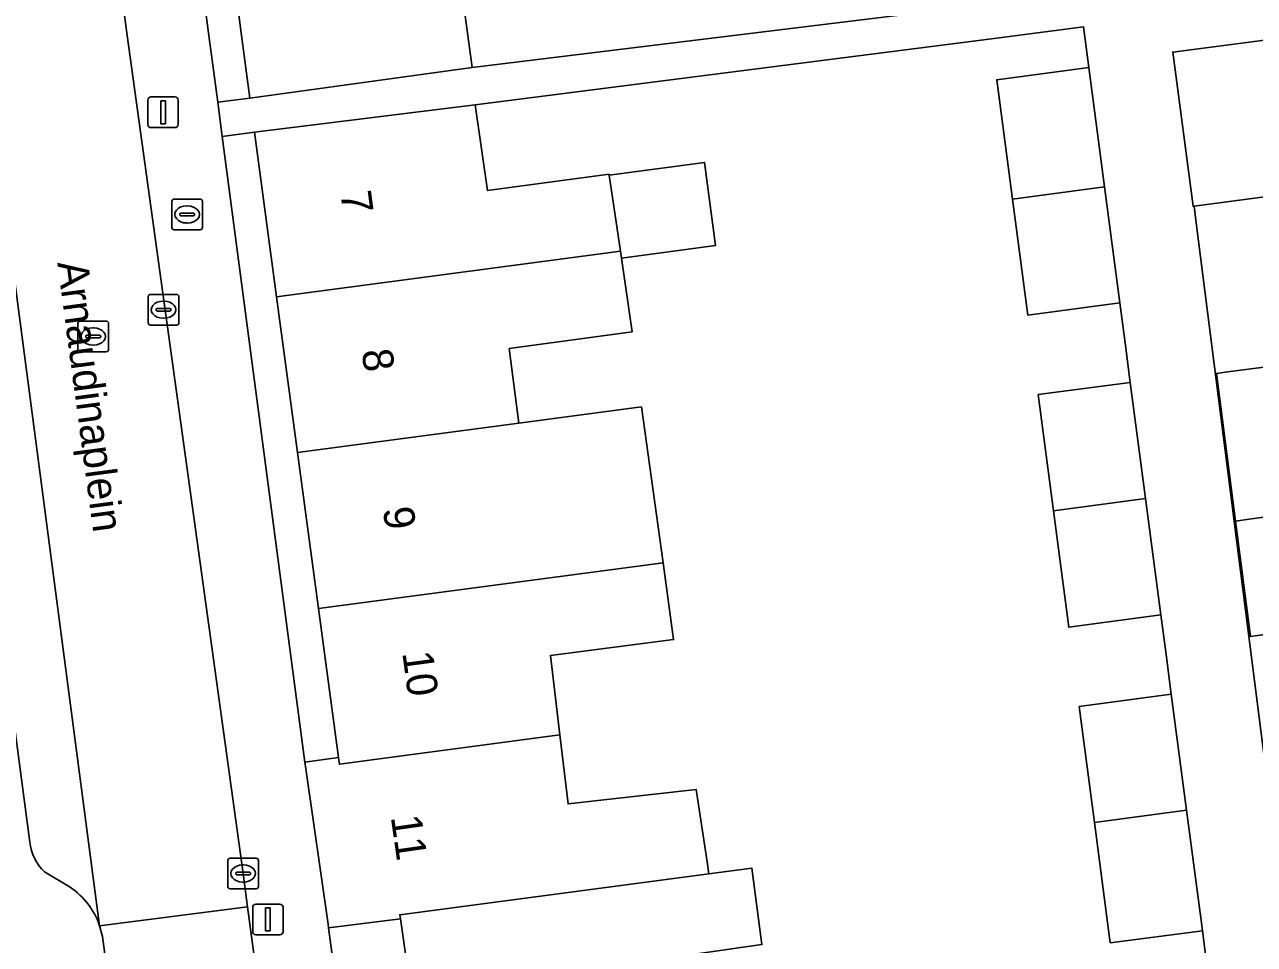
# Model space of a CAD drawing. Extents: x 163147 to 163550, y 380933 to 381639.
# Drawn here: x 163423.12 to 163463.29, y 381220.32 to 381250.36 of the extents above; entities that cross this region are included whole.
import ezdxf

# ---------------------------------------------------------------- set-up
doc = ezdxf.new("R2010")
doc.units = 0
for name, color, linetype in [('IMGEO_Brandkraan', 7, 'Continuous'), ('IMGEO_Erf', 7, 'Continuous'), ('IMGEO_Kolk', 7, 'Continuous'), ('IMGEO_Lichtmast', 7, 'Continuous'), ('IMGEO_Openbare_ruimte_label', 7, 'Continuous'), ('IMGEO_Pand', 7, 'Continuous'), ('IMGEO_Pand_nummerreeks', 7, 'Continuous'), ('IMGEO_Parkeervlak_open', 7, 'Continuous'), ('IMGEO_Rijbaan_lokaal_open', 7, 'Continuous'), ('IMGEO_Rioolput', 7, 'Continuous'), ('IMGEO_Voetpad_open', 7, 'Continuous')]:
    doc.layers.add(name, color=color, linetype=linetype)

msp = doc.modelspace()

# ---------------------------------------------------------------- linework, layer by layer
at = {"layer": 'IMGEO_Brandkraan'}
for p, q in [((163427.933, 381243.732), (163427.933, 381244.584)), ((163428.008, 381244.658), (163428.86, 381244.658)), ((163428.421, 381244.438), (163428.446, 381244.438)), ((163428.934, 381244.584), (163428.934, 381243.732)), ((163428.192, 381244.152), (163428.192, 381244.164)), ((163428.63, 381244.115), (163428.232, 381244.115)), ((163428.235, 381244.201), (163428.633, 381244.201)), ((163428.676, 381244.164), (163428.676, 381244.152)), ((163428.86, 381243.658), (163428.008, 381243.658)), ((163428.444, 381243.878), (163428.419, 381243.878))]:
    msp.add_line(p, q, dxfattribs=at)
for points in [[(163427.933, 381243.732), (163427.933, 381244.584)], [(163428.008, 381244.658), (163428.86, 381244.658)], [(163428.934, 381244.584), (163428.934, 381243.732)], [(163428.86, 381243.658), (163428.008, 381243.658)]]:
    msp.add_lwpolyline(points, dxfattribs=at)
for centre, radius, start, end in [((163428.01, 381244.582), 0.0765, 91.552, 178.448), ((163428.01, 381244.582), 0.0765, 91.552, 178.448), ((163428.858, 381244.582), 0.0765, 1.552, 88.448), ((163428.858, 381244.582), 0.0765, 1.552, 88.448), ((163428.232, 381244.161), 0.0403, 85.8775, 175.7526), ((163428.229, 381244.151), 0.0366, 178.938, 274.7102), ((163428.633, 381244.158), 0.043, 264.8664, 352.4533), ((163428.637, 381244.163), 0.0386, 1.7309, 96.639), ((163428.01, 381243.734), 0.0765, 181.552, 268.448), ((163428.01, 381243.734), 0.0765, 181.552, 268.448), ((163428.858, 381243.734), 0.0765, 271.552, 358.448), ((163428.858, 381243.734), 0.0765, 271.552, 358.448)]:
    msp.add_arc(centre, radius, start, end, dxfattribs=at)
for centre, major_axis, ratio, start_param, end_param in [((163428.42, 381244.158), (-0.387, 0.002), 0.722429, 4.712389, 7.853982), ((163428.445, 381244.158), (-0.39, 0.002), 0.717154, 1.570796, 4.712389)]:
    msp.add_ellipse(centre, major_axis=major_axis, ratio=ratio, start_param=start_param, end_param=end_param, dxfattribs=at)
at = {"layer": 'IMGEO_Erf'}
for points in [[(163428.498, 381263.148), (163427.838, 381268.207), (163426.754, 381268.057), (163429.143, 381250), (163429.432, 381247.82), (163430.478, 381247.959), (163430.212, 381250), (163429.825, 381252.969), (163429.161, 381258.058)], [(163431.352, 381241.467), (163430.629, 381246.841), (163429.579, 381246.702), (163432.283, 381226.275), (163433.376, 381226.422), (163432.721, 381231.291), (163432.037, 381236.379)], [(163465.674, 381234.559), (163466.161, 381230.788), (163463.165, 381230.376), (163462.678, 381234.147), (163462.055, 381238.969), (163462.505, 381239.027), (163465.054, 381239.356)], [(163435.398, 381221.16), (163433.055, 381220.865), (163433.713, 381215.942), (163436.097, 381216.261)]]:
    msp.add_lwpolyline(points, close=True, dxfattribs=at)
for points in [[(163437.371, 381251.695), (163437.604, 381250), (163437.747, 381248.957), (163457.58, 381251.397)], [(163461.71, 381219.908), (163461.597, 381220.769), (163458.588, 381220.373), (163458.532, 381220.791), (163458.07, 381224.302), (163457.572, 381228.088), (163460.58, 381228.488), (163460.409, 381229.79), (163460.239, 381231.079), (163457.231, 381230.679), (163456.731, 381234.48), (163456.231, 381238.275), (163459.24, 381238.674), (163459.07, 381239.968), (163458.899, 381241.268), (163455.89, 381240.869), (163455.392, 381244.658), (163454.879, 381248.558), (163457.887, 381248.955), (163457.712, 381250.283), (163454.704, 381249.887), (163437.843, 381247.74), (163438.242, 381244.937), (163442.214, 381245.472), (163442.219, 381245.44), (163445.335, 381245.854), (163445.695, 381243.147), (163442.618, 381242.733), (163442.972, 381240.326), (163438.955, 381239.775), (163439.267, 381237.339), (163443.273, 381237.871), (163443.977, 381232.786), (163444.325, 381230.277), (163440.299, 381229.756), (163440.61, 381227.16), (163440.879, 381224.909), (163445.064, 381225.378), (163445.419, 381223.013), (163445.477, 381222.629), (163446.874, 381222.815), (163447.21, 381220.316)], [(163464.284, 381244.821), (163461.325, 381244.431), (163461.395, 381243.883), (163465.785, 381209.444)]]:
    msp.add_lwpolyline(points, dxfattribs=at)
at = {"layer": 'IMGEO_Kolk'}
for p, q in [((163427.162, 381240.621), (163427.162, 381241.473)), ((163427.237, 381241.547), (163428.089, 381241.547)), ((163427.65, 381241.327), (163427.675, 381241.327)), ((163428.163, 381241.473), (163428.163, 381240.621)), ((163427.421, 381241.041), (163427.421, 381241.053)), ((163427.859, 381241.004), (163427.461, 381241.004)), ((163427.464, 381241.09), (163427.862, 381241.09)), ((163427.905, 381241.053), (163427.905, 381241.041)), ((163428.089, 381240.547), (163427.237, 381240.547)), ((163427.673, 381240.767), (163427.648, 381240.767)), ((163429.761, 381222.21), (163429.761, 381223.062)), ((163429.836, 381223.136), (163430.688, 381223.136)), ((163430.249, 381222.916), (163430.274, 381222.916)), ((163430.762, 381223.062), (163430.762, 381222.21)), ((163430.02, 381222.63), (163430.02, 381222.642)), ((163430.458, 381222.593), (163430.06, 381222.593)), ((163430.063, 381222.679), (163430.461, 381222.679)), ((163430.272, 381222.356), (163430.247, 381222.356)), ((163430.504, 381222.642), (163430.504, 381222.63)), ((163430.688, 381222.136), (163429.836, 381222.136))]:
    msp.add_line(p, q, dxfattribs=at)
for points in [[(163427.162, 381240.621), (163427.162, 381241.473)], [(163427.237, 381241.547), (163428.089, 381241.547)], [(163428.163, 381241.473), (163428.163, 381240.621)], [(163428.089, 381240.547), (163427.237, 381240.547)], [(163429.761, 381222.21), (163429.761, 381223.062)], [(163429.836, 381223.136), (163430.688, 381223.136)], [(163430.762, 381223.062), (163430.762, 381222.21)], [(163430.688, 381222.136), (163429.836, 381222.136)]]:
    msp.add_lwpolyline(points, dxfattribs=at)
for centre, radius, start, end in [((163427.239, 381241.471), 0.0765, 91.552, 178.448), ((163427.239, 381241.471), 0.0765, 91.552, 178.448), ((163428.087, 381241.471), 0.0765, 1.552, 88.448), ((163428.087, 381241.471), 0.0765, 1.552, 88.448), ((163427.461, 381241.05), 0.0403, 85.8775, 175.7526), ((163427.458, 381241.04), 0.0366, 178.938, 274.7102), ((163427.862, 381241.047), 0.043, 264.8664, 352.4533), ((163427.866, 381241.052), 0.0386, 1.7309, 96.639), ((163427.239, 381240.623), 0.0765, 181.552, 268.448), ((163427.239, 381240.623), 0.0765, 181.552, 268.448), ((163428.087, 381240.623), 0.0765, 271.552, 358.448), ((163428.087, 381240.623), 0.0765, 271.552, 358.448), ((163429.838, 381223.06), 0.0765, 91.552, 178.448), ((163429.838, 381223.06), 0.0765, 91.552, 178.448), ((163430.686, 381223.06), 0.0765, 1.552, 88.448), ((163430.686, 381223.06), 0.0765, 1.552, 88.448), ((163430.06, 381222.639), 0.0403, 85.8775, 175.7526), ((163430.057, 381222.629), 0.0366, 178.938, 274.7102), ((163430.461, 381222.636), 0.043, 264.8664, 352.4533), ((163430.465, 381222.641), 0.0386, 1.7309, 96.639), ((163429.838, 381222.212), 0.0765, 181.552, 268.448), ((163429.838, 381222.212), 0.0765, 181.552, 268.448), ((163430.686, 381222.212), 0.0765, 271.552, 358.448), ((163430.686, 381222.212), 0.0765, 271.552, 358.448)]:
    msp.add_arc(centre, radius, start, end, dxfattribs=at)
for centre, major_axis, ratio, start_param, end_param in [((163427.649, 381241.047), (-0.387, 0.002), 0.722429, 4.712389, 7.853982), ((163427.674, 381241.047), (-0.39, 0.002), 0.717154, 1.570796, 4.712389), ((163430.248, 381222.636), (-0.387, 0.002), 0.722429, 4.712389, 7.853982), ((163430.273, 381222.636), (-0.39, 0.002), 0.717154, 1.570796, 4.712389)]:
    msp.add_ellipse(centre, major_axis=major_axis, ratio=ratio, start_param=start_param, end_param=end_param, dxfattribs=at)
at = {"layer": 'IMGEO_Lichtmast'}
for p, q in [((163427.152, 381247.093), (163427.152, 381247.893)), ((163427.152, 381247.893), (163427.152, 381247.093)), ((163427.252, 381247.993), (163428.042, 381247.993)), ((163428.042, 381247.993), (163427.252, 381247.993)), ((163428.142, 381247.893), (163428.142, 381247.093)), ((163428.142, 381247.093), (163428.142, 381247.893)), ((163428.042, 381246.993), (163427.252, 381246.993)), ((163427.252, 381246.993), (163428.042, 381246.993)), ((163430.575, 381220.736), (163430.575, 381221.536)), ((163430.575, 381221.536), (163430.575, 381220.736)), ((163430.675, 381221.636), (163431.465, 381221.636)), ((163431.465, 381221.636), (163430.675, 381221.636)), ((163431.565, 381221.536), (163431.565, 381220.736)), ((163431.565, 381220.736), (163431.565, 381221.536)), ((163431.465, 381220.636), (163430.675, 381220.636)), ((163430.675, 381220.636), (163431.465, 381220.636))]:
    msp.add_line(p, q, dxfattribs=at)
for points in [[(163427.572, 381247.868), (163427.722, 381247.868), (163427.722, 381247.118), (163427.572, 381247.118), (163427.572, 381247.868)], [(163430.995, 381221.511), (163431.145, 381221.511), (163431.145, 381220.761), (163430.995, 381220.761), (163430.995, 381221.511)]]:
    msp.add_lwpolyline(points, dxfattribs=at)
for centre, start, end in [((163427.252, 381247.893), 90, 180), ((163427.252, 381247.893), 90, 180), ((163428.042, 381247.893), 0, 90), ((163428.042, 381247.893), 360, 90), ((163427.252, 381247.093), 180, 270), ((163427.252, 381247.093), 180, 270), ((163428.042, 381247.093), 270, 0), ((163428.042, 381247.093), 270, 0), ((163430.675, 381221.536), 90, 180), ((163430.675, 381221.536), 90, 180), ((163431.465, 381221.536), 0, 90), ((163431.465, 381221.536), 360, 90), ((163430.675, 381220.736), 180, 270), ((163430.675, 381220.736), 180, 270), ((163431.465, 381220.736), 270, 0), ((163431.465, 381220.736), 270, 0)]:
    msp.add_arc(centre, 0.1, start, end, dxfattribs=at)
at = {"layer": 'IMGEO_Pand'}
for points in [[(163441.11, 381254.487), (163429.825, 381252.969), (163430.212, 381250), (163430.478, 381247.959), (163437.747, 381248.957), (163437.604, 381250), (163437.371, 381251.695), (163441.405, 381252.221)], [(163463.624, 381249.828), (163463.621, 381249.851), (163460.626, 381249.457), (163461.289, 381244.426), (163461.325, 381244.431), (163464.284, 381244.821)], [(163457.887, 381248.955), (163454.879, 381248.558), (163455.392, 381244.658), (163458.4, 381245.057)], [(163437.843, 381247.74), (163430.629, 381246.841), (163431.352, 381241.467), (163442.585, 381242.958), (163442.219, 381245.44), (163442.214, 381245.472), (163438.242, 381244.937)], [(163445.335, 381245.854), (163442.219, 381245.44), (163442.585, 381242.958), (163442.618, 381242.733), (163445.695, 381243.147)], [(163458.4, 381245.057), (163455.392, 381244.658), (163455.89, 381240.869), (163458.899, 381241.268)], [(163438.955, 381239.775), (163442.972, 381240.326), (163442.618, 381242.733), (163442.585, 381242.958), (163431.352, 381241.467), (163432.037, 381236.379), (163439.267, 381237.339)], [(163462.678, 381234.147), (163463.127, 381234.209), (163465.674, 381234.559), (163465.054, 381239.356), (163462.505, 381239.027), (163462.055, 381238.969)], [(163459.24, 381238.674), (163456.231, 381238.275), (163456.731, 381234.48), (163459.739, 381234.88)], [(163443.273, 381237.871), (163439.267, 381237.339), (163432.037, 381236.379), (163432.721, 381231.291), (163443.977, 381232.786)], [(163459.739, 381234.88), (163456.731, 381234.48), (163457.231, 381230.679), (163460.239, 381231.079)], [(163465.674, 381234.559), (163463.127, 381234.209), (163462.678, 381234.147), (163463.165, 381230.376), (163466.161, 381230.788)], [(163440.299, 381229.756), (163444.325, 381230.277), (163443.977, 381232.786), (163432.721, 381231.291), (163433.376, 381226.422), (163433.406, 381226.203), (163440.61, 381227.16)], [(163460.58, 381228.488), (163457.572, 381228.088), (163458.07, 381224.302), (163461.079, 381224.702)], [(163445.064, 381225.378), (163440.879, 381224.909), (163440.61, 381227.16), (163433.406, 381226.203), (163433.376, 381226.422), (163432.283, 381226.275), (163432.314, 381226.058), (163433.039, 381220.977), (163433.055, 381220.865), (163435.398, 381221.16), (163435.38, 381221.288), (163445.477, 381222.629), (163445.419, 381223.013)], [(163461.079, 381224.702), (163458.07, 381224.302), (163458.532, 381220.791), (163458.588, 381220.373), (163461.597, 381220.769), (163461.542, 381221.187), (163461.498, 381221.519)], [(163443.033, 381219.718), (163447.21, 381220.316), (163446.874, 381222.815), (163445.477, 381222.629), (163435.38, 381221.288), (163435.398, 381221.16), (163436.097, 381216.261), (163441.052, 381216.932), (163443.357, 381217.244)]]:
    msp.add_lwpolyline(points, close=True, dxfattribs=at)
at = {"layer": 'IMGEO_Parkeervlak_open'}
for points in [[(163425.575, 381220.93), (163421.736, 381250), (163416.892, 381286.034)], [(163415.374, 381283.357), (163419.801, 381250), (163423.297, 381223.661)], [(163423.769, 381222.691), (163424.614, 381222.186)]]:
    msp.add_lwpolyline(points, dxfattribs=at)
for centre, radius, start, end in [((163424.857, 381223.82), 1.568, 185.8234, 226.0715), ((163423.196, 381220.106), 2.518, 19.1153, 55.7259)]:
    msp.add_arc(centre, radius, start, end, dxfattribs=at)
at = {"layer": 'IMGEO_Rijbaan_lokaal_open'}
for points in [[(163421.495, 381287.123), (163416.832, 381286.494), (163416.892, 381286.034), (163421.736, 381250), (163425.575, 381220.93), (163430.41, 381221.543), (163430.261, 381222.635), (163426.471, 381250)], [(163430.773, 381218.81), (163430.41, 381221.543), (163425.575, 381220.93), (163425.67, 381220.579), (163425.989, 381218.194)]]:
    msp.add_lwpolyline(points, close=True, dxfattribs=at)
at = {"layer": 'IMGEO_Rioolput'}
for p, q in [((163424.867, 381239.748), (163424.867, 381240.6)), ((163424.942, 381240.674), (163425.794, 381240.674)), ((163425.355, 381240.454), (163425.38, 381240.454)), ((163425.868, 381240.6), (163425.868, 381239.748)), ((163425.126, 381240.168), (163425.126, 381240.18)), ((163425.564, 381240.131), (163425.166, 381240.131)), ((163425.169, 381240.217), (163425.567, 381240.217)), ((163425.61, 381240.18), (163425.61, 381240.168)), ((163425.794, 381239.674), (163424.942, 381239.674)), ((163425.378, 381239.894), (163425.353, 381239.894))]:
    msp.add_line(p, q, dxfattribs=at)
for points in [[(163424.867, 381239.748), (163424.867, 381240.6)], [(163424.942, 381240.674), (163425.794, 381240.674)], [(163425.868, 381240.6), (163425.868, 381239.748)], [(163425.794, 381239.674), (163424.942, 381239.674)]]:
    msp.add_lwpolyline(points, dxfattribs=at)
for centre, radius, start, end in [((163424.944, 381240.598), 0.0765, 91.552, 178.448), ((163424.944, 381240.598), 0.0765, 91.552, 178.448), ((163425.792, 381240.598), 0.0765, 1.552, 88.448), ((163425.792, 381240.598), 0.0765, 1.552, 88.448), ((163425.166, 381240.177), 0.0403, 85.8775, 175.7526), ((163425.163, 381240.167), 0.0366, 178.938, 274.7102), ((163425.567, 381240.174), 0.043, 264.8664, 352.4533), ((163425.571, 381240.179), 0.0386, 1.7309, 96.639), ((163424.944, 381239.75), 0.0765, 181.552, 268.448), ((163424.944, 381239.75), 0.0765, 181.552, 268.448), ((163425.792, 381239.75), 0.0765, 271.552, 358.448), ((163425.792, 381239.75), 0.0765, 271.552, 358.448)]:
    msp.add_arc(centre, radius, start, end, dxfattribs=at)
for centre, major_axis, ratio, start_param, end_param in [((163425.354, 381240.174), (-0.387, 0.002), 0.722429, 4.712389, 7.853982), ((163425.379, 381240.174), (-0.39, 0.002), 0.717154, 1.570796, 4.712389)]:
    msp.add_ellipse(centre, major_axis=major_axis, ratio=ratio, start_param=start_param, end_param=end_param, dxfattribs=at)
at = {"layer": 'IMGEO_Voetpad_open'}
for points in [[(163419.541, 381301.698), (163419.608, 381301.196), (163421.129, 381289.848), (163421.495, 381287.123), (163426.471, 381250), (163430.261, 381222.635), (163430.41, 381221.543), (163430.773, 381218.81), (163432.818, 381203.407), (163434.853, 381188.435), (163435.404, 381184.201), (163435.633, 381182.277), (163435.88, 381180.272), (163436.282, 381176.303), (163436.423, 381174.825), (163436.736, 381171.03), (163436.749, 381170.87), (163436.756, 381170.797), (163436.763, 381170.724), (163437.048, 381167.531), (163437.11, 381166.833)], [(163438.198, 381182.356), (163438.023, 381183.666), (163435.32, 381203.921), (163435.296, 381204.102), (163434.616, 381209.181), (163434.596, 381209.333), (163433.922, 381214.377), (163433.713, 381215.942), (163433.055, 381220.865), (163433.039, 381220.977), (163432.314, 381226.058), (163432.283, 381226.275), (163429.579, 381246.702), (163429.432, 381247.82), (163429.143, 381250), (163426.754, 381268.057), (163426.086, 381273.18), (163426.051, 381273.449), (163425.393, 381278.278), (163425.235, 381279.434), (163424.816, 381282.506), (163423.226, 381294.162)], [(163423.297, 381223.661), (163419.801, 381250), (163415.374, 381283.357)], [(163457.58, 381251.397), (163437.747, 381248.957), (163430.478, 381247.959), (163429.432, 381247.82), (163429.579, 381246.702), (163430.629, 381246.841), (163437.843, 381247.74), (163454.704, 381249.887), (163457.712, 381250.283), (163457.887, 381248.955), (163458.4, 381245.057), (163458.899, 381241.268), (163459.07, 381239.968), (163459.24, 381238.674), (163459.739, 381234.88), (163460.239, 381231.079), (163460.409, 381229.79), (163460.58, 381228.488), (163461.079, 381224.702), (163461.498, 381221.519), (163461.542, 381221.187), (163461.597, 381220.769), (163461.71, 381219.908)], [(163465.785, 381209.444), (163461.395, 381243.883), (163461.325, 381244.431), (163461.289, 381244.426), (163460.626, 381249.457), (163463.621, 381249.851)], [(163424.614, 381222.186), (163423.769, 381222.691)], [(163426.029, 381217.897), (163425.989, 381218.194), (163425.67, 381220.579), (163425.575, 381220.93)]]:
    msp.add_lwpolyline(points, dxfattribs=at)
for centre, radius, start, end in [((163424.857, 381223.82), 1.568, 185.8234, 226.0715), ((163423.196, 381220.106), 2.518, 19.1153, 55.7259)]:
    msp.add_arc(centre, radius, start, end, dxfattribs=at)

# ---------------------------------------------------------------- texts
at = {"layer": 'IMGEO_Openbare_ruimte_label'}
msp.add_text('Arnaudinaplein', height=1, rotation=277.5871, dxfattribs=at).set_placement((163424.193, 381242.583))
at = {"layer": 'IMGEO_Pand_nummerreeks'}
for s, rotation, p in [('7', 277.6602, (163433.437, 381244.871)), ('8', 277.6602, (163434.131, 381239.708)), ('9', 277.6602, (163434.826, 381234.552)), ('10', 277.6602, (163435.459, 381229.845)), ('11', 278.1186, (163435.083, 381224.488))]:
    msp.add_text(s, height=1, rotation=rotation, dxfattribs=at).set_placement(p)

doc.saveas('drawing.dxf')
